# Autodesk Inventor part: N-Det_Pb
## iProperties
Shininess: 64.0
Length Units: 11269
Angle Units: 11279
Time Units: 11290
Mass Units: 11283
Length Display Precision: 3
Angle Display Precision: 2
Compacted: True
Part Number: N-Det_Pb
Document SubType Name: Modeling
Created: 2005-04
Material: Lead
Designer: John Blackburn
Manufacturer: Standard
Standards Organization: Custom
Density: 0.0
Volumn: 0.0
Area: 0.0
PropertySet Name: Model Information
Control State: 0
Master: False
Checked Out: False
Author: John Blackburn
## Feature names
1. Extrusion1
